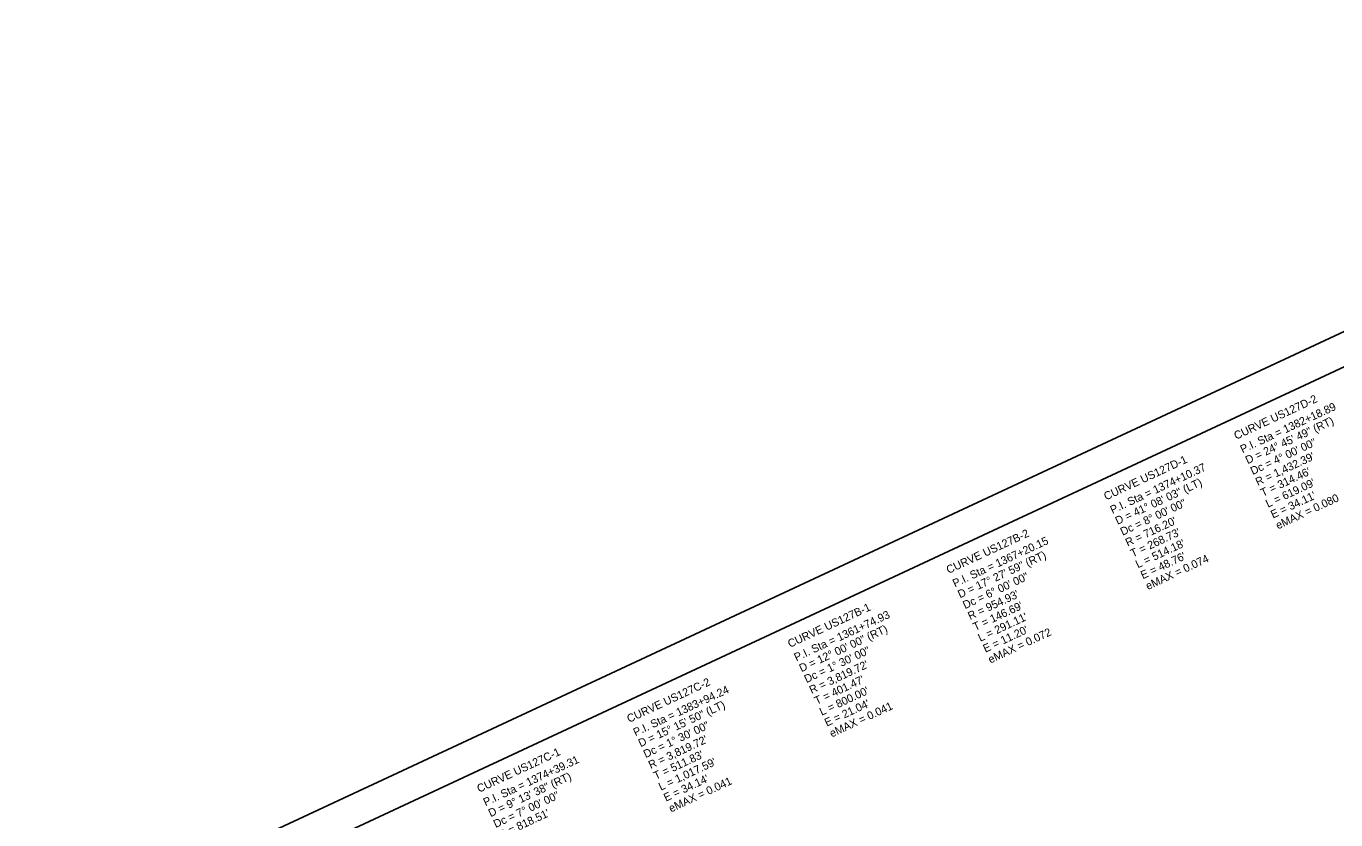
# Model space of a CAD drawing. Extents: x -310467776 to 1403491, y -322263105 to 578683.
# Drawn here: x 1391457 to 1397595, y 574964 to 578683 of the extents above; entities that cross this region are included whole.
import ezdxf

# ---------------------------------------------------------------- set-up
doc = ezdxf.new("R2010")
doc.units = 0
for name, color, linetype in [('SH_Border', 7, 'Continuous'), ('SH_Cut_Line', 7, 'Continuous'), ('SH_Text', 7, 'Continuous')]:
    doc.layers.add(name, color=color, linetype=linetype)

msp = doc.modelspace()

# ---------------------------------------------------------------- linework, layer by layer
at = {"layer": 'SH_Border'}
msp.add_lwpolyline([(1391928.5, 574427), (1400629, 578484.1), (1403291.5, 572774.4), (1394591, 568717.3)], close=True, dxfattribs=at)
at = {"layer": 'SH_Cut_Line'}
msp.add_lwpolyline([(1394246.5, 568391.1), (1403490.9, 572701.8), (1400701.6, 578683.5), (1391457.2, 574372.8)], close=True, dxfattribs=at)

# ---------------------------------------------------------------- texts
at = {"layer": 'SH_Text'}
for s, p in [('CURVE US127D-2', (1397127.9, 576745.1)), ('P.I. Sta = 1382+18.89', (1397157.5, 576681.6)), ('D = 24° 45\' 49" (RT)', (1397181.3, 576630.7)), ('Dc = 4° 00\' 00"', (1397205.1, 576579.7)), ('CURVE US127D-1', (1396518.3, 576460.8)), ("R = 1,432.39'", (1397228.8, 576528.7)), ('P.I. Sta = 1374+10.37', (1396547.8, 576397.4)), ("T = 314.46'", (1397252.6, 576477.7)), ('D = 41° 08\' 03" (LT)', (1396571.6, 576346.4)), ("L = 619.09'", (1397276.4, 576426.7)), ("E = 34.11'", (1397300.2, 576375.8)), ('eMAX = 0.080', (1397323.9, 576324.8)), ('Dc = 8° 00\' 00"', (1396595.4, 576295.4)), ("R = 716.20'", (1396619.2, 576244.4)), ('CURVE US127B-2', (1395780, 576116.5)), ("T = 268.73'", (1396642.9, 576193.4)), ('P.I. Sta = 1367+20.15', (1395809.6, 576053.1)), ("L = 514.18'", (1396666.7, 576142.5)), ('D = 17° 27\' 59" (RT)', (1395833.4, 576002.1)), ("E = 48.76'", (1396690.5, 576091.5)), ('eMAX = 0.074', (1396714.3, 576040.5)), ('Dc = 6° 00\' 00"', (1395857.1, 575951.1)), ("R = 954.93'", (1395880.9, 575900.2)), ('CURVE US127B-1', (1395036.9, 575770)), ('P.I. Sta = 1361+74.93', (1395066.5, 575706.6)), ("T = 146.69'", (1395904.7, 575849.2)), ("L = 291.11'", (1395928.4, 575798.2)), ('D = 12° 00\' 00" (RT)', (1395090.3, 575655.6)), ("E = 11.20'", (1395952.2, 575747.2)), ('eMAX = 0.072', (1395976, 575696.2)), ('Dc = 1° 30\' 00"', (1395114, 575604.6)), ("R = 3,819.72'", (1395137.8, 575553.6)), ('CURVE US127C-2', (1394283.1, 575418.5)), ("T = 401.47'", (1395161.6, 575502.7)), ('P.I. Sta = 1383+94.24', (1394312.7, 575355.1)), ("L = 800.00'", (1395185.4, 575451.7)), ('D = 15° 15\' 50" (LT)', (1394336.5, 575304.1)), ("E = 21.04'", (1395209.1, 575400.7)), ('eMAX = 0.041', (1395232.9, 575349.7)), ('Dc = 1° 30\' 00"', (1394360.2, 575253.1)), ("R = 3,819.72'", (1394384, 575202.1)), ('CURVE US127C-1', (1393580.3, 575090.8)), ('P.I. Sta = 1374+39.31', (1393609.9, 575027.4)), ("T = 511.83'", (1394407.8, 575151.2)), ("L = 1,017.59'", (1394431.5, 575100.2)), ('D = 9° 13\' 38" (RT)', (1393633.7, 574976.4)), ("E = 34.14'", (1394455.3, 575049.2)), ('eMAX = 0.041', (1394479.1, 574998.2)), ('Dc = 7° 00\' 00"', (1393657.5, 574925.4)), ("R = 818.51'", (1393681.2, 574874.4))]:
    msp.add_text(s, height=37.5, rotation=25, dxfattribs=at).set_placement(p)

doc.saveas('drawing.dxf')
